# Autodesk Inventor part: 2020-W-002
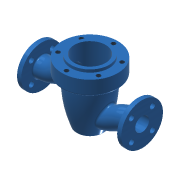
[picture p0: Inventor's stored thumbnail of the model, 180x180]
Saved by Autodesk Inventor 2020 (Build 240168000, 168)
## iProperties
Created: 2013-12
Part Number: 2020-W-002
Material: Żeliwo sferoidalne
Document SubType Name: Modeling
Designer: F.Stasiak
Density: 7.1 g/cm^3
Appearance: Cyjan
Description: Korpus zaworu KZX 300
Mass: 4426.49 g
Surface Area: 2478.62 cm^2
Volume: 1633.39 cm^3
Manager: www.cadconsulting.pl
Company: Fabian Stasiak CAD Consulting
Author: F.Stasiak
Subject: Zbiór ćwiczeń. Autodesk Inventor 2020. Kurs podstawowy
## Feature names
1. Obrót1 [Revolution]
2. Przeciągnięcie1
3. Wyciągnięcie proste1 [Extrusion]
4. Przeciągnięcie2
5. Wyciągnięcie proste2 [Extrusion]
6. Obrót2 [Revolution]
7. Przeciągnięcie3
8. Przeciągnięcie4
9. Otwór1 [Hole]
10. Odbicie lustrzane1 [Mirror]
11. Otwór2 [Hole]
12. Szyk kołowy1 [Circular Pattern]
13. Zaokrąglenie1 [Fillet]
14. Zaokrąglenie2 [Fillet]
15. Zaokrąglenie3 [Fillet]
16. Zaokrąglenie4 [Fillet]
## Parameters: d2 = 75 mm, d5 = 15 mm, d10 = 8 mm, d12 = 90 deg, d16 = 55 mm, d19 = 13 mm, d21 = 13 mm, d22 = 0, d23 = 12 mm, d24 = 0, d26 = 13 mm, d27 = 13 mm, d29 = 0, d30 = 12 mm, d31 = 0, d32 = 90 deg, d33 = 0, d34 = 0, d35 = 85 mm, d36 = 15 mm, d37 = 6 mm, d38 = 4 mm, d39 = 2 mm, d40 = 90 deg, d41 = 8 mm, d42 = 118 deg, d43 = 135 mm, d44 = 11.835 mm, d45 = 25 mm, d46 = 4 mm, d47 = 2 mm, d48 = 90 deg, d50 = 118 deg, d52 = 360 deg, d54 = 3 mm, d55 = 5 mm, d56 = 5 mm, d57 = 5 mm, d58 = 0, d59 = 0, d60 = 0, d61 = 0
